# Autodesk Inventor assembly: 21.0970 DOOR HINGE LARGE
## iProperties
Created: 2010-07
Part Number: 21.0970 DOOR HINGE LARGE
Document SubType Name: Assembly
Designer: Administrator
Author: Administrator
